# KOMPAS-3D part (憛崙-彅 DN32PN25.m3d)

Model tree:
1. Объединить компоненты:1  (labels: СЕНС-ПФ DN32PN25)

Referenced files in D:\Савин\!СЕНСОР\3D для заказчика\!Новый перечень\СЕНС-ПФ\DN32\: СЕНС-ПФ DN32PN25.a3d
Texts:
  СЕНС-ПФ DN32PN25
  ООО НПП Сенсор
